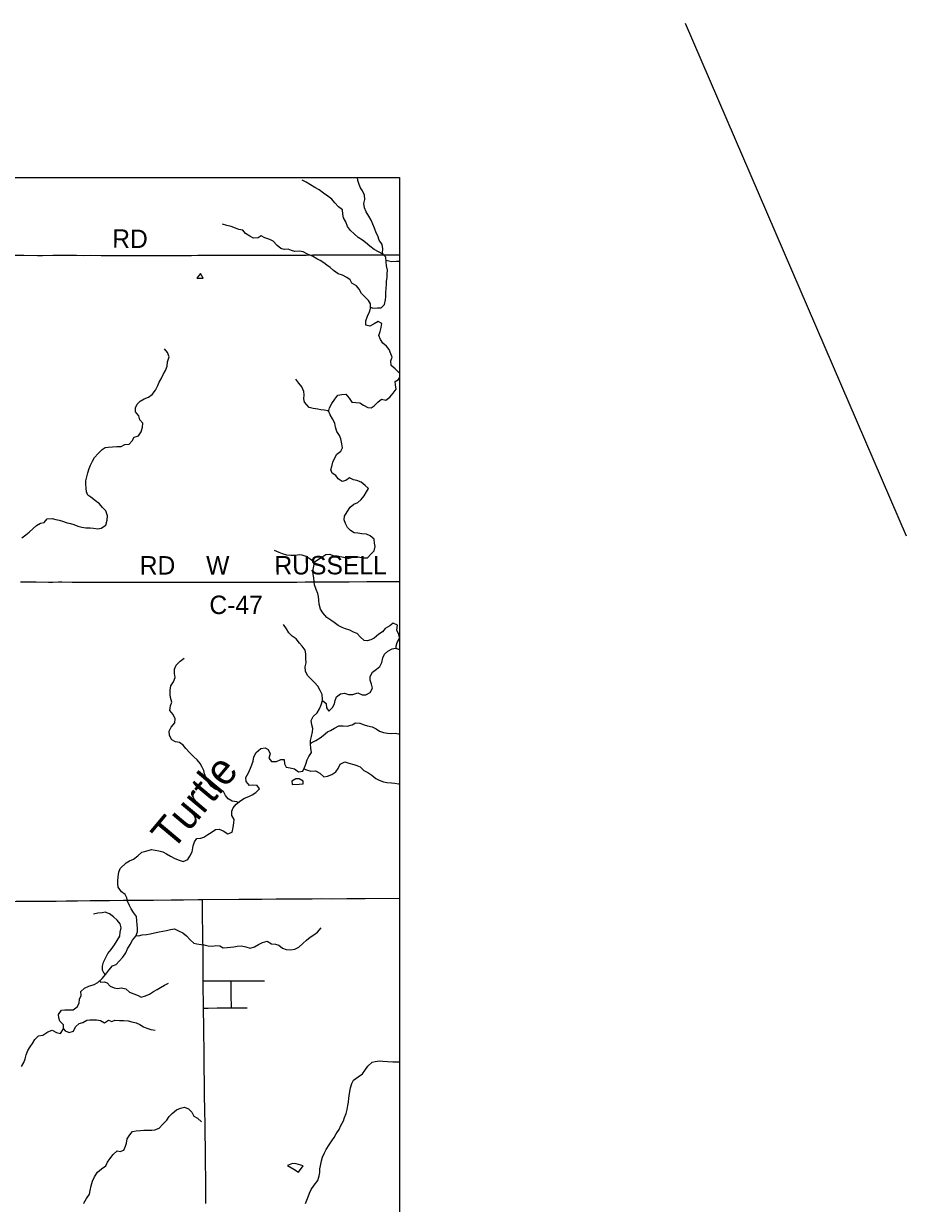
# Model space of a CAD drawing. Extents: x -87 to 2145, y -2128 to 440.
# Drawn here: x 199.6 to 271.5, y -908.7 to -812.6 of the extents above; entities that cross this region are included whole.
import ezdxf

# ---------------------------------------------------------------- set-up
doc = ezdxf.new("R2010")
doc.units = 0
for name, color, linetype in [('Default', 7, 'Continuous'), ('GM_X_County_Road', 7, 'Continuous'), ('GM_X_County_Road_Text', 7, 'Continuous'), ('GM_X_Minor_Lake', 7, 'Continuous'), ('GM_X_Minor_River', 7, 'Continuous'), ('GM_X_Minor_River_Text', 7, 'Continuous'), ('GM_X_State_Route', 7, 'Continuous'), ('GM_X_Township_Road', 7, 'Continuous'), ('SC_Scratch1', 7, 'Continuous')]:
    doc.layers.add(name, color=color, linetype=linetype)

msp = doc.modelspace()

# ---------------------------------------------------------------- linework, layer by layer
at = {"layer": 'Default'}
msp.add_line((271.487, -854.393), (253.484, -812.644), dxfattribs=at)
at = {"layer": 'GM_X_County_Road'}
for points in [[(198.548, -831.507), (199.598, -831.511), (200.697, -831.521), (201.107, -831.521), (201.96, -831.52), (202.862, -831.52), (203.879, -831.512), (204.437, -831.522), (205.028, -831.52), (205.897, -831.524), (206.832, -831.521), (207.718, -831.523), (208.653, -831.53), (209.884, -831.531), (210.442, -831.527), (211.245, -831.523), (212, -831.525), (213.231, -831.521), (213.765, -831.517), (215.002, -831.507), (217.266, -831.51), (217.889, -831.512), (219.022, -831.504), (219.826, -831.504), (220.482, -831.496), (222.598, -831.495), (223.139, -831.488), (224.091, -831.479), (224.632, -831.48), (224.895, -831.48), (225.206, -831.476), (225.469, -831.473), (225.813, -831.477), (226.157, -831.481), (226.665, -831.485), (226.862, -831.484), (227.059, -831.482), (227.305, -831.479), (227.403, -831.478), (227.681, -831.476), (227.812, -831.475), (227.927, -831.48), (228.041, -831.477), (228.287, -831.476), (228.747, -831.479), (229.042, -831.477), (229.238, -831.478), (229.845, -831.484), (230.183, -831.483)], [(199.316, -858.115), (200.596, -858.128), (201.597, -858.134), (201.941, -858.137), (202.4, -858.129), (202.679, -858.13), (203.515, -858.132), (204.352, -858.131), (204.894, -858.135), (205.501, -858.137), (206.469, -858.144), (206.911, -858.14), (207.765, -858.137), (208.421, -858.14), (209.569, -858.137), (210.57, -858.14), (211.784, -858.131), (213.375, -858.14), (213.795, -858.135)], [(213.795, -858.135), (214.72, -858.144), (215.442, -858.14), (216.607, -858.137), (217.313, -858.133), (218.871, -858.138), (219.773, -858.142), (221.037, -858.138), (221.824, -858.136), (222.513, -858.129), (223.152, -858.125), (223.431, -858.125), (223.471, -858.124), (224.21, -858.118), (224.701, -858.116), (225.439, -858.119), (226.078, -858.115), (227.521, -858.102), (228.259, -858.099), (229.637, -858.088), (230.178, -858.078), (230.183, -858.078)]]:
    msp.add_lwpolyline(points, dxfattribs=at)
at = {"layer": 'GM_X_Minor_Lake'}
for p, q in [((214.188, -833.375), (213.973, -833)), ((222.35, -874.576), (222.333, -874.355))]:
    msp.add_line(p, q, dxfattribs=at)
for points in [[(213.973, -833), (213.674, -833.38)], [(213.674, -833.38), (214.188, -833.375)], [(222.333, -874.355), (222.005, -874.168), (221.735, -874.173), (221.42, -874.366), (221.433, -874.634)], [(221.433, -874.634), (222.018, -874.609), (222.35, -874.576)], [(222.35, -905.676), (221.782, -905.522), (221.462, -905.495), (221.062, -905.656)], [(221.062, -905.656), (221.594, -905.958), (221.951, -906.215), (222.35, -905.676)]]:
    msp.add_lwpolyline(points, dxfattribs=at)
at = {"layer": 'GM_X_Minor_River'}
for points in [[(227.829, -835.73), (228.029, -835.812), (228.391, -835.796), (228.693, -835.81), (228.966, -835.513), (229.06, -835.153), (229.082, -834.883), (229.085, -834.522), (229.097, -834.262), (229.141, -833.882), (229.143, -833.622), (229.176, -833.332), (229.198, -833.041), (229.211, -832.731), (229.133, -832.38), (229.106, -832.039), (229.069, -831.678), (228.83, -831.414), (228.479, -831.24), (228.119, -831.056), (227.78, -830.781), (227.43, -830.477), (227.171, -830.283), (226.831, -830.059), (226.501, -829.775), (226.202, -829.501), (225.964, -829.167), (225.806, -828.805), (225.628, -828.462), (225.58, -828.161), (225.543, -827.82), (225.213, -827.576), (224.934, -827.242), (224.666, -826.939), (224.346, -826.705), (223.996, -826.46), (223.657, -826.196), (223.287, -825.991), (222.926, -825.777), (222.597, -825.563), (222.266, -825.388)], [(228.871, -831.461), (228.81, -831.304), (228.833, -830.984), (228.786, -830.633), (228.528, -830.279), (228.42, -829.937), (228.301, -829.686), (228.144, -829.313), (228.006, -828.971), (227.868, -828.659), (227.7, -828.327), (227.481, -827.984), (227.333, -827.661), (227.296, -827.3), (227.359, -826.961), (227.332, -826.62), (227.174, -826.268), (227.025, -826.015), (226.907, -825.764), (226.799, -825.412), (226.771, -825.188)], [(230.183, -841.126), (230.137, -841.056), (229.848, -840.762), (229.518, -840.488), (229.471, -840.126), (229.604, -839.807), (229.486, -839.556), (229.358, -839.193), (229.129, -838.93), (228.84, -838.667), (228.631, -838.364), (228.503, -838.042), (228.617, -837.712), (228.69, -837.393), (228.752, -837.083), (228.462, -836.909), (228.119, -837.095), (227.786, -837.282), (227.455, -837.208), (227.448, -836.867), (227.582, -836.478), (227.745, -836.119), (227.828, -835.86), (227.831, -835.479), (227.673, -835.197), (227.353, -834.903), (227.094, -834.639), (226.896, -834.286), (226.677, -834.013), (226.307, -833.789), (226.159, -833.527), (225.899, -833.333), (225.539, -833.139), (225.198, -833.015), (224.808, -832.759), (224.549, -832.516), (224.279, -832.313), (224.019, -832.119), (223.739, -831.936), (223.459, -831.802), (223.089, -831.597), (222.738, -831.453), (222.328, -831.228), (222.017, -831.184), (221.675, -831.22), (221.384, -831.127), (221.114, -831.013), (220.792, -831.039), (220.531, -830.966), (220.222, -830.722), (219.903, -830.378), (219.613, -830.224), (219.232, -830.09), (218.932, -829.926), (218.669, -830.103), (218.287, -830.109), (217.986, -829.965), (217.637, -829.74), (217.418, -829.467), (217.107, -829.403), (216.836, -829.3), (216.465, -829.165), (216.134, -829.091), (215.783, -828.987)], [(229.092, -831.906), (229.317, -831.981), (229.568, -832.034), (229.941, -831.988), (230.183, -831.991)], [(205.053, -851.219), (204.794, -851.044), (204.697, -850.782), (204.671, -850.481), (204.624, -850.16), (204.648, -849.89), (204.786, -849.241), (204.92, -848.882), (205.004, -848.613), (205.169, -848.275), (205.353, -847.978), (205.638, -847.662), (205.953, -847.326), (206.216, -847.18), (206.467, -847.144), (206.809, -847.12), (207.16, -847.095), (207.512, -847.091), (207.825, -846.926), (208.167, -846.901), (208.401, -846.644), (208.585, -846.327), (208.938, -846.212), (209.132, -845.885), (209.257, -845.516), (209.271, -845.186), (209.023, -844.931), (208.947, -844.599), (208.68, -844.264), (208.693, -843.944), (208.817, -843.645), (209.071, -843.389), (209.385, -843.214), (209.738, -843.079), (210.052, -842.844), (210.307, -842.507), (210.502, -842.119), (210.615, -841.861), (210.769, -841.593), (210.934, -841.235), (211.139, -840.907), (211.253, -840.559), (211.288, -840.188), (211.433, -839.78), (211.286, -839.437), (211.049, -839.132)], [(223.243, -856.515), (223.506, -856.324), (223.931, -856.049), (224.183, -855.901), (224.525, -855.865), (224.826, -856.009), (225.117, -855.992), (225.629, -856.108), (226, -856.213), (226.282, -856.126), (226.543, -856.089), (226.825, -856.092), (227.266, -856.167), (227.588, -856.151), (227.892, -855.844), (228.136, -855.586), (228.209, -855.227), (228.161, -854.976), (228.134, -854.635), (227.804, -854.371), (227.494, -854.237), (227.112, -854.213), (226.791, -854.159), (226.5, -854.115), (226.2, -853.942), (225.951, -853.678), (225.783, -853.366), (225.685, -853.074), (225.717, -852.774), (225.932, -852.406), (226.176, -852.038), (226.469, -851.781), (226.792, -851.645), (227.065, -851.418), (227.309, -851.1), (227.513, -850.782), (227.656, -850.513), (227.397, -850.27), (227.078, -849.986), (226.727, -849.861), (226.436, -849.818), (226.126, -849.654), (225.822, -849.871), (225.51, -849.957), (225.19, -849.723), (225.012, -849.451), (224.712, -849.267), (224.593, -849.005), (224.666, -848.726), (224.76, -848.356), (224.903, -848.067), (225.086, -847.729), (225.41, -847.482), (225.543, -847.203), (225.486, -846.862), (225.408, -846.47), (225.31, -846.199), (225.082, -845.876), (224.984, -845.524), (224.917, -845.192), (224.739, -844.85), (224.54, -844.507), (224.402, -844.175), (224.041, -844.12), (223.79, -844.118), (223.529, -844.054), (223.168, -844.01), (222.837, -843.906), (222.438, -843.471), (222.4, -843.2), (222.413, -842.879), (222.405, -842.609), (222.238, -842.226), (221.979, -841.923), (221.75, -841.619)], [(224.431, -844.244), (224.392, -844.265), (224.495, -843.935), (224.669, -843.587), (224.933, -843.249), (225.167, -842.901), (225.479, -842.845), (225.821, -842.819), (226.099, -843.163), (226.318, -843.486), (226.629, -843.499), (226.971, -843.523), (227.26, -843.727), (227.611, -843.911), (227.872, -843.944), (228.124, -843.777), (228.438, -843.48), (228.732, -843.233), (229.083, -843.307), (229.407, -843.061), (229.67, -842.743), (229.914, -842.425), (229.867, -842.064), (229.839, -841.804), (230.102, -841.626), (230.183, -841.499)], [(199.432, -854.523), (199.756, -854.298), (200.019, -854.062), (200.354, -853.777), (200.618, -853.541), (200.942, -853.336), (201.244, -853.271), (201.478, -852.994), (201.9, -852.971), (202.2, -853.036), (202.471, -853.1), (202.741, -853.175), (203.111, -853.301), (203.391, -853.365), (203.651, -853.45), (203.991, -853.595), (204.311, -853.651), (204.632, -853.726), (204.983, -853.712), (205.264, -853.756), (205.625, -853.792), (205.876, -853.756), (206.271, -853.492), (206.376, -853.103), (206.411, -852.743), (206.265, -852.32), (205.997, -852.065), (205.76, -851.761), (205.421, -851.515), (205.053, -851.219)], [(230.183, -862.659), (230.127, -862.398), (229.979, -862.046), (230.033, -861.636), (229.672, -861.492), (229.409, -861.709), (229.015, -861.915), (228.812, -862.183), (228.499, -862.39), (228.134, -862.696), (227.842, -862.843), (227.56, -862.929), (227.299, -862.886), (226.99, -862.593), (226.741, -862.339), (226.43, -862.206), (226.13, -862.062), (225.799, -861.958), (225.529, -861.845), (225.189, -861.671), (224.879, -861.437), (224.59, -861.243), (224.27, -861.009), (223.931, -860.655), (223.743, -860.332), (223.646, -859.941), (223.629, -859.62), (223.581, -859.309), (223.523, -859.058), (223.405, -858.747), (223.268, -858.374), (223.25, -858.104), (223.213, -857.793), (223.144, -857.532), (223.137, -857.261), (223.211, -856.832), (223.264, -856.532), (222.924, -856.257), (222.574, -856.043), (222.264, -855.939), (222.003, -855.906), (221.731, -855.963), (221.329, -855.979), (221.017, -855.945), (220.667, -855.841), (220.396, -855.738), (220.016, -855.573)], [(223.905, -867.795), (223.91, -867.673), (223.893, -867.302), (223.725, -866.97), (223.547, -866.627), (223.269, -866.304), (223.01, -866.081), (222.681, -865.737), (222.533, -865.394), (222.506, -865.044), (222.579, -864.714), (222.552, -864.354), (222.546, -863.993), (222.498, -863.692), (222.27, -863.359), (222.051, -863.106), (221.782, -862.773), (221.443, -862.549), (221.184, -862.275), (220.996, -861.933), (220.748, -861.6)], [(229.911, -863.519), (229.927, -863.357), (229.99, -863.067), (230.183, -862.728)], [(222.793, -872.344), (223.017, -872.016), (222.97, -871.665), (222.933, -871.345), (222.935, -871.035), (223.008, -870.715), (223.102, -870.326), (223.135, -870.066), (223.037, -869.755), (222.98, -869.414), (223.154, -869.095), (223.478, -868.789), (223.672, -868.451), (223.805, -868.132), (223.909, -867.783), (224.208, -868.036), (224.256, -868.367), (224.424, -868.64), (224.718, -868.363), (224.891, -868.054), (224.954, -867.795), (225.057, -867.496), (225.391, -867.249), (225.703, -867.173), (226.034, -867.287), (226.385, -867.301), (226.789, -867.165), (227.139, -867.31), (227.44, -867.313), (227.794, -867.127), (227.988, -866.769), (227.91, -866.447), (227.803, -866.126), (227.795, -865.825), (227.979, -865.467), (228.313, -865.231), (228.586, -865.004), (228.75, -864.695), (228.824, -864.316), (228.977, -864.007), (229.251, -863.76), (229.604, -863.584), (229.876, -863.507), (230.183, -863.616)], [(217.054, -876.091), (216.926, -876.043), (216.566, -875.976), (216.218, -875.798), (216.022, -875.514), (215.847, -875.191), (215.507, -875.123), (215.168, -875.016), (214.851, -874.76), (214.606, -874.425), (214.452, -874.081), (214.307, -873.748), (214.261, -873.497), (214.096, -873.164), (213.96, -872.911), (213.695, -872.605), (213.438, -872.37), (213.103, -872.033), (212.788, -871.686), (212.561, -871.431), (212.264, -871.205), (211.944, -871.148), (211.646, -870.992), (211.452, -870.638), (211.428, -870.287), (211.594, -869.96), (211.881, -869.606), (211.927, -869.267), (211.762, -868.934), (211.467, -868.597), (211.544, -868.229), (211.649, -867.911), (211.535, -867.548), (211.5, -867.287), (211.506, -866.947), (211.552, -866.588), (211.768, -866.273), (211.905, -865.905), (211.85, -865.574), (211.866, -865.244), (211.992, -864.906), (212.309, -864.583), (212.634, -864.339)], [(222.933, -871.315), (223.044, -871.216), (223.387, -871.04), (223.721, -870.823), (223.984, -870.636), (224.318, -870.34), (224.571, -870.223), (224.894, -870.036), (225.237, -869.84), (225.589, -869.844), (225.92, -869.878), (226.323, -869.752), (226.606, -869.606), (226.958, -869.62), (227.318, -869.764), (227.579, -869.847), (227.95, -869.941), (228.3, -870.095), (228.57, -870.279), (228.89, -870.403), (229.212, -870.436), (229.563, -870.47), (229.834, -870.453), (230.095, -870.486), (230.183, -870.537)], [(206.503, -889.752), (206.807, -889.395), (207.12, -889.289), (207.354, -889.022), (207.648, -888.685), (207.883, -888.348), (208.036, -888.009), (208.251, -887.662), (208.445, -887.314), (208.699, -886.987), (208.833, -886.638), (208.856, -886.299), (208.818, -886.048), (208.801, -885.728), (208.754, -885.387), (208.516, -885.064), (208.328, -884.742), (208.19, -884.47), (208.022, -884.128), (207.984, -883.867), (207.836, -883.596), (207.547, -883.362), (207.269, -882.989), (207.241, -882.688), (207.244, -882.438), (207.257, -882.138), (207.33, -881.759), (207.444, -881.47), (207.93, -881.006), (208.203, -880.839), (208.506, -880.712), (208.86, -880.446), (209.185, -880.13), (209.517, -880.064), (209.99, -879.929), (210.282, -879.973), (210.583, -880.016), (210.904, -880.1), (211.214, -880.264), (211.523, -880.468), (211.873, -880.642), (212.244, -880.796), (212.554, -880.91), (212.938, -880.724), (213.121, -880.456), (213.306, -880.098), (213.38, -879.629), (213.484, -879.29), (213.667, -879.022), (213.999, -878.986), (214.251, -878.909), (214.575, -878.703), (214.857, -878.546), (215.192, -878.28), (215.493, -878.253), (215.834, -878.407), (216.193, -878.631), (216.546, -878.516), (216.65, -878.137), (216.684, -877.737), (216.727, -877.467), (216.539, -877.145), (216.542, -876.804), (216.635, -876.535), (216.889, -876.218), (217.273, -875.922), (217.566, -875.726), (217.919, -875.59), (218.192, -875.473), (218.495, -875.286), (218.789, -874.969), (218.581, -874.717), (218.249, -874.673), (217.978, -874.7), (217.709, -874.386), (217.682, -874.046), (217.876, -873.688), (218.041, -873.3), (218.164, -873.021), (218.267, -872.712), (218.31, -872.372), (218.504, -872.024), (218.899, -871.698), (219.241, -871.652), (219.492, -871.775), (219.659, -872.127), (219.556, -872.477), (219.774, -872.739), (220.156, -872.764), (220.519, -872.598), (220.781, -872.591), (220.818, -872.932), (220.956, -873.213), (221.287, -873.267), (221.648, -873.352), (221.958, -873.585), (222.32, -873.549), (222.443, -873.231), (222.546, -872.972), (222.68, -872.603), (222.793, -872.344)], [(222.392, -873.362), (222.622, -873.443), (222.963, -873.537), (223.355, -873.501), (223.705, -873.696), (224.014, -873.999), (224.336, -873.953), (224.689, -873.817), (225.013, -873.581), (225.196, -873.323), (225.35, -872.964), (225.733, -872.788), (226.064, -872.882), (226.475, -872.987), (226.726, -873.08), (226.976, -873.193), (227.295, -873.477), (227.615, -873.651), (227.925, -873.864), (228.274, -874.149), (228.544, -874.272), (228.895, -874.396), (229.165, -874.469), (229.547, -874.494), (229.798, -874.516), (230.119, -874.58), (230.183, -874.594)], [(206.241, -890.109), (206.138, -890.028), (205.98, -889.746), (205.983, -889.426), (206.087, -889.107), (206.261, -888.719), (206.435, -888.391), (206.699, -888.054), (206.984, -887.687), (207.198, -887.339), (207.393, -886.992), (207.446, -886.642), (207.519, -886.313), (207.422, -885.972), (207.194, -885.689), (206.895, -885.405), (206.565, -885.171), (206.215, -885.037), (205.953, -885.074), (205.611, -885.11), (205.268, -885.196)], [(208.728, -886.913), (208.931, -886.95), (209.233, -886.883), (209.585, -886.837), (209.887, -886.781), (210.219, -886.715), (210.602, -886.639), (210.914, -886.583), (211.196, -886.516), (211.529, -886.43), (211.861, -886.384), (212.191, -886.548), (212.531, -886.702), (212.84, -886.966), (213.139, -887.27), (213.428, -887.553), (213.679, -887.596), (214.02, -887.67), (214.281, -887.693), (214.612, -887.757), (214.973, -887.801), (215.225, -887.744), (215.566, -887.778), (215.836, -887.922), (216.158, -887.895), (216.42, -887.878), (216.681, -887.851), (216.963, -887.795), (217.325, -887.779), (217.676, -887.853), (218.037, -887.957), (218.37, -887.841), (218.703, -887.665), (219.036, -887.509), (219.419, -887.393), (219.759, -887.598), (220.09, -887.641), (220.361, -887.715), (220.65, -887.968), (220.961, -888.062), (221.302, -888.106), (221.655, -888.03), (221.998, -887.874), (222.322, -887.588), (222.616, -887.301), (222.92, -887.074), (223.213, -886.858), (223.496, -886.651), (223.811, -886.314)], [(199.404, -897.599), (199.578, -897.271), (199.681, -896.982), (199.785, -896.634), (199.919, -896.305), (200.092, -895.987), (200.286, -895.729), (200.47, -895.402), (200.774, -895.105), (201.126, -895.039), (201.541, -894.774), (201.894, -894.638), (202.244, -894.823), (202.575, -894.896), (202.81, -894.529), (202.813, -894.209), (202.504, -893.895), (202.426, -893.644), (202.398, -893.374), (202.643, -893.007), (202.935, -892.98), (203.276, -892.984), (203.608, -892.968), (203.932, -892.742), (204.096, -892.434), (204.109, -892.124), (204.242, -891.806), (204.215, -891.485), (204.529, -891.219), (204.882, -891.053), (205.306, -890.908), (205.619, -890.752), (205.974, -890.416), (206.258, -890.089), (206.503, -889.752)], [(205.774, -890.605), (205.82, -890.724), (206.122, -890.688), (206.372, -890.791), (206.621, -891.064), (206.952, -891.188), (207.202, -891.231), (207.545, -891.195), (207.906, -891.279), (208.205, -891.553), (208.535, -891.686), (208.896, -891.821), (209.146, -891.944), (209.488, -891.838), (209.811, -891.702), (210.155, -891.496), (210.448, -891.319), (210.711, -891.162), (211.044, -890.976), (211.377, -890.81)], [(202.803, -894.539), (202.949, -894.691), (203.289, -894.815), (203.622, -894.719), (203.806, -894.371), (204.08, -894.104), (204.382, -894.008), (204.716, -893.822), (204.967, -893.795), (205.229, -893.798), (205.51, -893.791), (205.841, -893.855), (206.161, -894.049), (206.485, -893.823), (206.755, -893.936), (207.008, -893.819), (207.379, -893.843), (207.711, -893.847), (208.072, -893.882), (208.383, -893.955), (208.724, -894.029), (209.034, -894.173), (209.344, -894.357), (209.595, -894.47), (209.935, -894.584), (210.276, -894.648)], [(222.527, -908.749), (222.582, -908.628), (222.76, -908.211), (222.845, -907.902), (222.981, -907.614), (223.238, -907.258), (223.536, -906.872), (223.633, -906.494), (223.687, -906.234), (223.702, -905.944), (223.757, -905.685), (223.834, -905.285), (223.909, -904.976), (224.066, -904.639), (224.211, -904.351), (224.468, -903.985), (224.675, -903.648), (224.861, -903.37), (225.036, -903.073), (225.263, -902.736), (225.419, -902.409), (225.617, -902.031), (225.722, -901.743), (225.838, -901.434), (225.924, -901.095), (225.979, -900.776), (226.024, -900.506), (226.07, -900.177), (226.116, -899.787), (226.204, -899.348), (226.301, -898.969), (226.446, -898.701), (226.832, -898.437), (227.178, -898.203), (227.374, -897.916), (227.621, -897.569), (227.958, -897.255), (228.21, -897.199), (228.583, -897.145), (228.844, -897.15), (229.225, -897.176), (229.657, -897.204), (229.958, -897.219), (230.183, -897.223)], [(204.47, -908.749), (204.477, -908.735), (204.7, -908.347), (204.942, -907.989), (204.994, -907.709), (205.076, -907.33), (205.169, -906.931), (205.351, -906.572), (205.594, -906.214), (205.906, -905.927), (206.258, -905.689), (206.39, -905.38), (206.602, -905.112), (206.864, -904.754), (207.187, -904.457), (207.437, -904.519), (207.718, -904.421), (207.88, -904.093), (207.962, -903.833), (208.014, -903.484), (208.216, -903.175), (208.428, -902.887), (208.739, -902.84), (209.09, -902.813), (209.351, -902.795), (209.672, -902.778), (210.012, -902.781), (210.263, -902.763), (210.605, -902.626), (210.917, -902.298), (211.24, -901.981), (211.432, -901.682), (211.664, -901.424), (212.026, -901.127), (212.357, -900.98), (212.679, -900.913), (212.989, -901.045), (213.268, -901.318), (213.426, -901.65), (213.736, -901.812), (214.055, -902.115)]]:
    msp.add_lwpolyline(points, dxfattribs=at)
at = {"layer": 'GM_X_State_Route'}
for points in [[(191.289, -884.233), (191.472, -884.222), (191.964, -884.208), (193.293, -884.19), (194.212, -884.179), (194.704, -884.178), (195.197, -884.182), (197.275, -884.161), (198.276, -884.144), (198.948, -884.138), (199.49, -884.134), (200.084, -884.137)], [(200.084, -884.137), (200.162, -884.137), (201.08, -884.129), (202.229, -884.119), (203.032, -884.109), (203.967, -884.095), (204.984, -884.084), (206.575, -884.077), (207.706, -884.054), (208.494, -884.047), (209.445, -884.042), (210.161, -884.035)], [(210.161, -884.035), (211.593, -884.022), (212.593, -884.014), (213.79, -883.996), (214.127, -883.993), (217.087, -883.979), (218.973, -883.964), (220.154, -883.952), (221.254, -883.942), (222.32, -883.942), (223.074, -883.934), (223.845, -883.924), (224.616, -883.926), (225.896, -883.919), (226.945, -883.91), (227.405, -883.904), (230.183, -883.897)]]:
    msp.add_lwpolyline(points, dxfattribs=at)
at = {"layer": 'GM_X_Township_Road'}
msp.add_line((216.496, -892.819), (217.787, -892.82), dxfattribs=at)
for points in [[(199.316, -858.115), (200.596, -858.128), (201.597, -858.134), (201.941, -858.137), (202.4, -858.129), (202.679, -858.13), (203.515, -858.132), (204.352, -858.131), (204.894, -858.135), (205.501, -858.137), (206.469, -858.144), (206.911, -858.14), (207.765, -858.137), (208.421, -858.14), (209.569, -858.137), (210.57, -858.14), (211.784, -858.131), (213.375, -858.14), (213.795, -858.135)], [(213.795, -858.135), (214.72, -858.144), (215.442, -858.14), (216.607, -858.137), (217.313, -858.133), (218.871, -858.138), (219.773, -858.142), (221.037, -858.138), (221.824, -858.136), (222.513, -858.129), (223.152, -858.125), (223.431, -858.125), (223.471, -858.124), (224.21, -858.118), (224.701, -858.116), (225.439, -858.119), (226.078, -858.115), (227.521, -858.102), (228.259, -858.099), (229.637, -858.088), (230.178, -858.078), (230.183, -858.078)], [(214.196, -890.619), (214.194, -890.373), (214.197, -889.635), (214.196, -889.209), (214.192, -888.766), (214.189, -888.259), (214.185, -887.866), (214.179, -887.325), (214.175, -887.046), (214.165, -886.636), (214.155, -886.145), (214.149, -885.915), (214.143, -885.637), (214.138, -885.341), (214.132, -884.915), (214.127, -883.993)], [(214.196, -890.619), (214.332, -890.618), (216.482, -890.612)], [(214.221, -892.839), (214.22, -892.768), (214.214, -892.111), (214.204, -891.505), (214.198, -890.931), (214.196, -890.619)], [(216.482, -890.612), (218.272, -890.626), (218.765, -890.625), (219.192, -890.62)], [(216.496, -892.819), (216.484, -891.745), (216.485, -891.631), (216.486, -891.484), (216.487, -891.254), (216.483, -890.739), (216.482, -890.612)], [(214.221, -892.839), (214.386, -892.838), (214.615, -892.836), (215.334, -892.821), (215.777, -892.822), (216.459, -892.819), (216.496, -892.819)], [(214.42, -908.749), (214.422, -908.38), (214.421, -907.888), (214.419, -907.674), (214.413, -907.084), (214.408, -906.756), (214.402, -906.412), (214.392, -905.772), (214.381, -904.772), (214.375, -904.066), (214.363, -903.263), (214.356, -902.754), (214.345, -902.18), (214.332, -901.328), (214.321, -900.786), (214.315, -900.311), (214.308, -899.704), (214.303, -899.294), (214.294, -898.671), (214.286, -897.95), (214.285, -897.064), (214.282, -896.359), (214.281, -896.08), (214.256, -895.096), (214.257, -894.555), (214.246, -894.095), (214.223, -893.21), (214.221, -892.839)]]:
    msp.add_lwpolyline(points, dxfattribs=at)
at = {"layer": 'SC_Scratch1'}
msp.add_lwpolyline([(-21.617, -825.188), (230.183, -825.188), (230.183, -1245.188), (-21.617, -1245.188)], close=True, dxfattribs=at)

# ---------------------------------------------------------------- texts
at = {"layer": 'GM_X_County_Road_Text'}
for s, rotation, p in [('RD', 359.50769, (206.779, -830.904)), ('RD', 0.00001, (209.026, -857.523)), ('W', 0.00001, (214.438, -857.523)), ('RUSSELL', 0.15825, (220.005, -857.522)), ('C-47', 0.00001, (214.702, -860.741))]:
    msp.add_text(s, height=1.5, rotation=rotation, dxfattribs=at).set_placement(p)
at = {"layer": 'GM_X_Minor_River_Text'}
msp.add_text('Turtle', height=2.5002, rotation=50.04508, dxfattribs=at).set_placement((211.685, -880.096))

doc.saveas('drawing.dxf')
